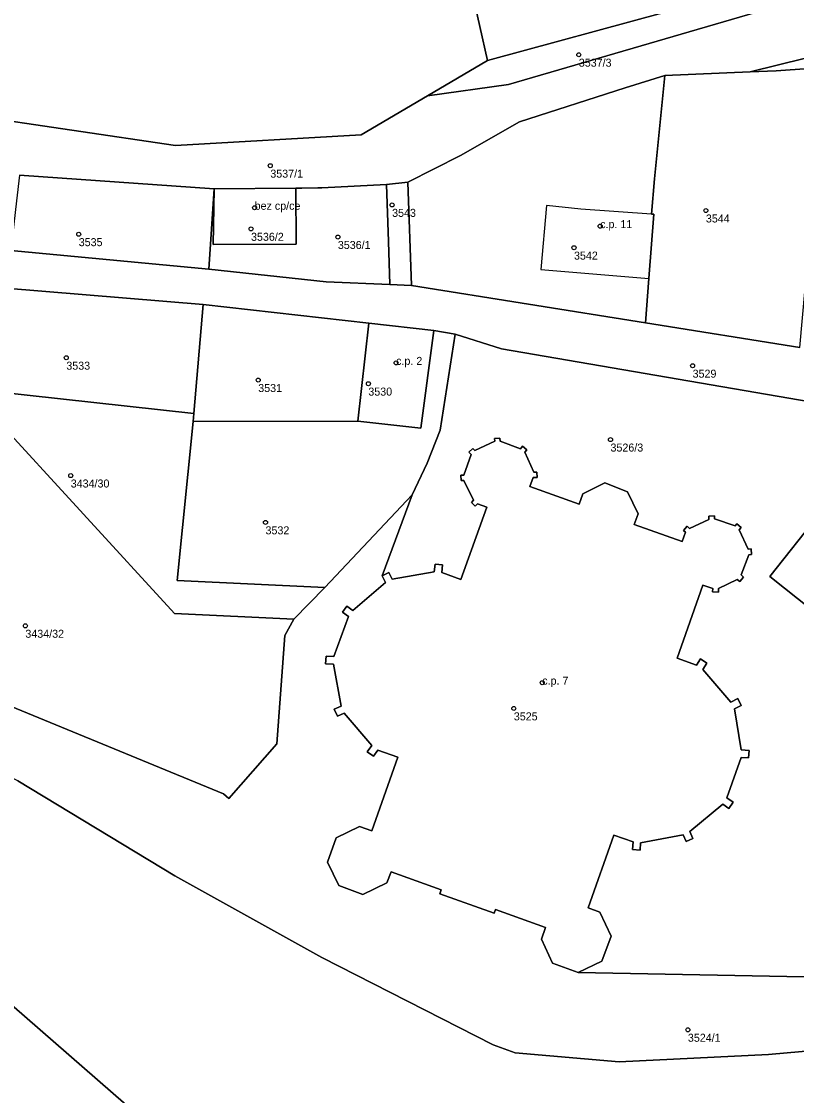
# Model space of a CAD drawing. Extents: x -878211 to -870363, y -1058464 to -1052522.
# Drawn here: x -876345.2 to -876248.4, y -1055057.5 to -1054923.3 of the extents above; entities that cross this region are included whole.
import ezdxf

# ---------------------------------------------------------------- set-up
doc = ezdxf.new("R2010")
doc.units = 0
for name, color, linetype in [('Definiční body', 7, 'Continuous'), ('Polygon budovy', 7, 'Continuous'), ('Polygon parcely', 7, 'Continuous')]:
    doc.layers.add(name, color=color, linetype=linetype)

msp = doc.modelspace()

# ---------------------------------------------------------------- linework, layer by layer
at = {"layer": 'Definiční body'}
for centre in [(-876275.58, -1054927.46994), (-876314.13, -1054941.32994), (-876316.09, -1054946.57994), (-876298.91, -1054946.22994), (-876259.7, -1054946.92994), (-876316.54, -1054949.21994), (-876272.91, -1054948.87994), (-876338.07, -1054949.88994), (-876305.69, -1054950.23994), (-876276.18, -1054951.56994), (-876339.62, -1054965.31994), (-876298.41, -1054965.95994), (-876261.36, -1054966.31994), (-876315.64, -1054968.10994), (-876301.88, -1054968.55994), (-876271.62, -1054975.54994), (-876339.07, -1054980.03994), (-876314.73, -1054985.88994), (-876344.74, -1054998.80994), (-876280.15, -1055005.90994), (-876283.7, -1055009.12994), (-876261.95, -1055049.27994)]:
    msp.add_circle(centre, 0.25, dxfattribs=at)
at = {"layer": 'Polygon budovy'}
for points in [[(-876321.14, -1054944.23), (-876321.25, -1054951.15), (-876310.9, -1054951.14), (-876310.92, -1054944.14)], [(-876280.32, -1054954.31), (-876266.83, -1054955.43), (-876266.2, -1054947.4), (-876266.5, -1054947.38), (-876275.33, -1054946.75), (-876279.63, -1054946.3)], [(-876293.7, -1054961.9), (-876301.81, -1054960.98), (-876303.2, -1054973.25), (-876295.3, -1054974.1)]]:
    msp.add_lwpolyline(points, close=True, dxfattribs=at)
for points in [[(-876274.43, -1055034.05), (-876271.2, -1055024.96), (-876268.78, -1055025.79), (-876268.87, -1055026.75), (-876267.92, -1055026.84), (-876267.86, -1055025.9), (-876262.55, -1055024.92), (-876262.17, -1055025.76), (-876261.32, -1055025.37), (-876261.69, -1055024.52), (-876257.58, -1055021.07), (-876256.82, -1055021.61), (-876256.31, -1055020.82), (-876257.09, -1055020.28), (-876255.31, -1055015.26), (-876254.38, -1055015.3), (-876254.31, -1055014.39), (-876255.27, -1055014.3), (-876256.11, -1055009.18), (-876255.27, -1055008.75), (-876255.69, -1055007.9), (-876256.57, -1055008.34), (-876260.08, -1055004.25), (-876259.58, -1055003.47), (-876260.36, -1055002.95), (-876260.88, -1055003.71), (-876263.27, -1055002.86), (-876260.09, -1054993.71), (-876258.83, -1054994.14), (-876258.86, -1054994.58), (-876258.13, -1054994.59), (-876258.12, -1054994.16), (-876255.77, -1054993.02), (-876255.44, -1054993.28), (-876254.98, -1054992.71), (-876255.3, -1054992.45), (-876254.35, -1054989.92), (-876254, -1054989.89), (-876254.04, -1054989.2), (-876254.43, -1054989.22), (-876255.55, -1054986.82), (-876255.28, -1054986.53), (-876255.84, -1054986.05), (-876256.06, -1054986.33), (-876258.61, -1054985.43), (-876258.62, -1054985.05), (-876259.32, -1054985.09), (-876259.32, -1054985.52), (-876261.73, -1054986.65), (-876262.05, -1054986.36), (-876262.5, -1054986.9), (-876262.23, -1054987.11), (-876262.67, -1054988.27), (-876268.67, -1054986.13), (-876268.18, -1054984.8), (-876269.48, -1054982.06), (-876272.32, -1054980.96), (-876275.07, -1054982.3), (-876275.55, -1054983.62), (-876281.68, -1054981.4), (-876281.27, -1054980.27), (-876280.78, -1054980.27), (-876280.84, -1054979.6), (-876281.22, -1054979.6), (-876282.32, -1054977.13), (-876282.08, -1054976.84), (-876282.62, -1054976.38), (-876282.87, -1054976.68), (-876285.4, -1054975.74), (-876285.44, -1054975.36), (-876286.11, -1054975.4), (-876286.09, -1054975.72), (-876288.56, -1054976.92), (-876288.82, -1054976.66), (-876289.32, -1054977.12), (-876289.03, -1054977.42), (-876289.94, -1054979.98), (-876290.33, -1054979.98), (-876290.29, -1054980.67), (-876289.95, -1054980.65), (-876288.73, -1054983.12), (-876289, -1054983.39), (-876288.51, -1054983.88), (-876288.24, -1054983.58), (-876287.06, -1054983.99), (-876290.32, -1054993.02), (-876292.71, -1054992.16), (-876292.6, -1054991.17), (-876293.54, -1054991.09), (-876293.64, -1054992.05), (-876298.89, -1054992.98), (-876299.31, -1054992.14), (-876300.15, -1054992.56), (-876299.72, -1054993.39), (-876303.83, -1054996.89), (-876304.57, -1054996.34), (-876305.12, -1054997.09), (-876304.36, -1054997.65), (-876306.18, -1055002.65), (-876307.15, -1055002.58), (-876307.22, -1055003.54)], [(-876307.22, -1055003.54), (-876306.24, -1055003.61), (-876305.27, -1055008.83), (-876306.15, -1055009.24), (-876305.74, -1055010.11), (-876304.89, -1055009.7), (-876301.46, -1055013.74), (-876302.01, -1055014.56), (-876301.22, -1055015.08), (-876300.69, -1055014.33), (-876298.21, -1055015.2), (-876301.45, -1055024.43), (-876302.99, -1055023.89), (-876305.92, -1055025.28), (-876306.98, -1055028.35), (-876305.58, -1055031.24), (-876302.56, -1055032.37), (-876299.57, -1055030.93), (-876299.03, -1055029.53), (-876292.76, -1055031.79), (-876292.94, -1055032.29), (-876286.14, -1055034.7), (-876285.98, -1055034.24), (-876279.73, -1055036.5), (-876280.25, -1055037.96), (-876278.88, -1055040.97), (-876275.67, -1055042.1), (-876272.69, -1055040.72), (-876271.53, -1055037.57), (-876272.96, -1055034.57), (-876274.43, -1055034.05)]]:
    msp.add_lwpolyline(points, dxfattribs=at)
at = {"layer": 'Polygon parcely'}
for points in [[(-876385.33, -1054930.06), (-876351.91, -1054934.98), (-876325.98, -1054938.79), (-876302.79, -1054937.47), (-876294.48, -1054932.58), (-876286.97, -1054928.17), (-876291.78, -1054906.9), (-876297.96, -1054890.06), (-876299.88, -1054875.09), (-876309.04, -1054869.25), (-876318.21, -1054867.84), (-876339.28, -1054874.2), (-876356, -1054887.75), (-876380.69, -1054897.58), (-876399.9, -1054901.85), (-876408.73, -1054905.38), (-876418.87, -1054910.9), (-876423.48, -1054914.13), (-876427.47, -1054915.93), (-876428.71, -1054917.43), (-876423.95, -1054924.24), (-876403.1, -1054932.35)], [(-876245.21, -1054919.74), (-876243.34, -1054905.33), (-876262.86, -1054909.66), (-876291.78, -1054906.9), (-876286.97, -1054928.17), (-876264.63, -1054922.12)], [(-876245.21, -1054919.74), (-876264.63, -1054922.12), (-876286.97, -1054928.17), (-876294.48, -1054932.58), (-876284.35, -1054931.17)], [(-876243.27, -1054928.94), (-876226.91, -1054926.9), (-876243.87, -1054927.05), (-876254.17, -1054929.61), (-876250.92, -1054929.47)], [(-876250.92, -1054929.47), (-876254.17, -1054929.61), (-876264.85, -1054930.05), (-876266.13, -1054942.96), (-876266.5, -1054947.38), (-876266.2, -1054947.4), (-876266.83, -1054955.43), (-876267.26, -1054960.95), (-876247.95, -1054964.03), (-876247.29, -1054956.62), (-876245.27, -1054933.93), (-876243.38, -1054933.76), (-876243.27, -1054928.94)], [(-876264.85, -1054930.05), (-876269.8, -1054931.6), (-876283.01, -1054935.86), (-876290.37, -1054940.07), (-876296.94, -1054943.38), (-876296.49, -1054956.28), (-876267.26, -1054960.95), (-876266.83, -1054955.43), (-876266.2, -1054947.4), (-876266.5, -1054947.38), (-876266.13, -1054942.96)], [(-876321.8, -1054954.26), (-876321.14, -1054944.23), (-876345.46, -1054942.49), (-876345.83, -1054945.71), (-876346.55, -1054951.9)], [(-876321.25, -1054951.15), (-876321.14, -1054944.23), (-876321.8, -1054954.26), (-876307.13, -1054955.82), (-876299.2, -1054956.16), (-876299.37, -1054950.78), (-876299.59, -1054943.69), (-876307.7, -1054944.11), (-876308.2, -1054944.11), (-876310.2, -1054944.13), (-876310.92, -1054944.14), (-876310.9, -1054951.14)], [(-876310.92, -1054944.14), (-876321.14, -1054944.23), (-876321.25, -1054951.15), (-876310.9, -1054951.14)], [(-876299.37, -1054950.78), (-876299.2, -1054956.16), (-876296.49, -1054956.28), (-876296.94, -1054943.38), (-876299.59, -1054943.69)], [(-876323.7, -1054972.29), (-876322.54, -1054958.67), (-876347.21, -1054956.62), (-876348.7, -1054969.52)], [(-876303.2, -1054973.25), (-876301.81, -1054960.98), (-876322.54, -1054958.67), (-876323.7, -1054972.29), (-876323.78, -1054973.29)], [(-876303.2, -1054973.25), (-876295.3, -1054974.1), (-876293.7, -1054961.9), (-876301.81, -1054960.98)], [(-876323.78, -1054973.29), (-876325.75, -1054993.15), (-876307.31, -1054994.01), (-876296.41, -1054982.45), (-876294.52, -1054978.5), (-876292.89, -1054974.37), (-876291.01, -1054962.38), (-876293.7, -1054961.9), (-876295.3, -1054974.1), (-876303.2, -1054973.25)], [(-876348.7, -1054969.52), (-876366.72, -1055000.87), (-876364.74, -1055001.39), (-876319.98, -1055019.81), (-876319.3, -1055020.38), (-876313.33, -1055013.57), (-876312.3, -1055000.03), (-876311.19, -1054997.97), (-876326.11, -1054997.28), (-876348.87, -1054972.47)], [(-876323.78, -1054973.29), (-876323.7, -1054972.29), (-876348.7, -1054969.52), (-876348.87, -1054972.47), (-876326.11, -1054997.28), (-876311.19, -1054997.97), (-876307.31, -1054994.01), (-876325.75, -1054993.15)], [(-876230.61, -1055019.14), (-876225.89, -1055023.06), (-876221.26, -1055017.49), (-876216.66, -1055021.3), (-876202.64, -1055032.79), (-876197.32, -1055029.35), (-876182.5, -1055017.11), (-876202.1, -1055003.26), (-876211.84, -1054995.38), (-876218.33, -1054990.08), (-876212.05, -1054982.01), (-876236.87, -1054973.88), (-876237.48, -1054974.65), (-876245.51, -1054984.81), (-876251.72, -1054992.65), (-876242.95, -1054999.62), (-876226.09, -1055013.5)], [(-876316.66, -1055102.83), (-876306.38, -1055081.71), (-876323.34, -1055066.32), (-876358.9, -1055035.38), (-876377.75, -1055027.25), (-876396.33, -1055052.17), (-876351.9, -1055057.99), (-876356.57, -1055092.43), (-876334.52, -1055096.3)]]:
    msp.add_lwpolyline(points, close=True, dxfattribs=at)
for points in [[(-876245.21, -1054919.74), (-876284.35, -1054931.17), (-876294.48, -1054932.58), (-876302.79, -1054937.47), (-876325.98, -1054938.79), (-876351.91, -1054934.98)], [(-876345.46, -1054942.49), (-876321.14, -1054944.23), (-876310.92, -1054944.14), (-876310.2, -1054944.13), (-876308.2, -1054944.11), (-876307.7, -1054944.11), (-876299.59, -1054943.69), (-876296.94, -1054943.38), (-876290.37, -1054940.07), (-876283.01, -1054935.86), (-876269.8, -1054931.6), (-876264.85, -1054930.05), (-876254.17, -1054929.61), (-876243.87, -1054927.05)], [(-876247.95, -1054964.03), (-876267.26, -1054960.95), (-876296.49, -1054956.28), (-876299.2, -1054956.16), (-876307.13, -1054955.82), (-876321.8, -1054954.26), (-876346.55, -1054951.9), (-876347.21, -1054956.62), (-876322.54, -1054958.67), (-876301.81, -1054960.98), (-876293.7, -1054961.9), (-876291.01, -1054962.38), (-876285.26, -1054964.19), (-876245.2, -1054971.07)], [(-876245.2, -1054971.07), (-876285.26, -1054964.19), (-876291.01, -1054962.38), (-876292.89, -1054974.37), (-876294.52, -1054978.5), (-876296.41, -1054982.45), (-876300.15, -1054992.56), (-876299.31, -1054992.14), (-876298.89, -1054992.98), (-876293.64, -1054992.05), (-876293.54, -1054991.09), (-876292.6, -1054991.17), (-876292.71, -1054992.16), (-876290.32, -1054993.02), (-876287.06, -1054983.99), (-876288.24, -1054983.58), (-876288.51, -1054983.88), (-876289, -1054983.39), (-876288.73, -1054983.12), (-876289.95, -1054980.65), (-876290.29, -1054980.67), (-876290.33, -1054979.98), (-876289.94, -1054979.98), (-876289.03, -1054977.42), (-876289.32, -1054977.12), (-876288.82, -1054976.66), (-876288.56, -1054976.92), (-876286.09, -1054975.72), (-876286.11, -1054975.4), (-876285.44, -1054975.36), (-876285.4, -1054975.74), (-876282.87, -1054976.68), (-876282.62, -1054976.38), (-876282.08, -1054976.84), (-876282.32, -1054977.13), (-876281.22, -1054979.6), (-876280.84, -1054979.6), (-876280.78, -1054980.27), (-876281.27, -1054980.27), (-876281.68, -1054981.4), (-876275.55, -1054983.62), (-876275.07, -1054982.3), (-876272.32, -1054980.96), (-876269.48, -1054982.06), (-876268.18, -1054984.8), (-876268.67, -1054986.13), (-876262.67, -1054988.27), (-876262.23, -1054987.11), (-876262.5, -1054986.9), (-876262.05, -1054986.36), (-876261.73, -1054986.65), (-876259.32, -1054985.52), (-876259.32, -1054985.09), (-876258.62, -1054985.05), (-876258.61, -1054985.43), (-876256.06, -1054986.33), (-876255.84, -1054986.05), (-876255.28, -1054986.53), (-876255.55, -1054986.82), (-876254.43, -1054989.22), (-876254.04, -1054989.2), (-876254, -1054989.89), (-876254.35, -1054989.92), (-876255.3, -1054992.45), (-876254.98, -1054992.71), (-876255.44, -1054993.28), (-876255.77, -1054993.02), (-876258.12, -1054994.16), (-876258.13, -1054994.59), (-876258.86, -1054994.58), (-876258.83, -1054994.14), (-876260.09, -1054993.71), (-876263.27, -1055002.86), (-876260.88, -1055003.71), (-876260.36, -1055002.95), (-876259.58, -1055003.47), (-876260.08, -1055004.25), (-876256.57, -1055008.34), (-876255.69, -1055007.9), (-876255.27, -1055008.75), (-876256.11, -1055009.18), (-876255.27, -1055014.3), (-876254.31, -1055014.39), (-876254.38, -1055015.3), (-876255.31, -1055015.26), (-876257.09, -1055020.28), (-876256.31, -1055020.82), (-876256.82, -1055021.61), (-876257.58, -1055021.07), (-876261.69, -1055024.52)], [(-876280.84, -1054979.6), (-876281.22, -1054979.6), (-876282.32, -1054977.13), (-876282.08, -1054976.84), (-876282.62, -1054976.38), (-876282.87, -1054976.68), (-876285.4, -1054975.74), (-876285.44, -1054975.36), (-876286.11, -1054975.4), (-876286.09, -1054975.72), (-876288.56, -1054976.92), (-876288.82, -1054976.66), (-876289.32, -1054977.12), (-876289.03, -1054977.42), (-876289.94, -1054979.98), (-876290.33, -1054979.98), (-876290.29, -1054980.67), (-876289.95, -1054980.65), (-876288.73, -1054983.12), (-876289, -1054983.39), (-876288.51, -1054983.88), (-876288.24, -1054983.58), (-876287.06, -1054983.99), (-876290.32, -1054993.02), (-876292.71, -1054992.16), (-876292.6, -1054991.17), (-876293.54, -1054991.09), (-876293.64, -1054992.05), (-876298.89, -1054992.98), (-876299.31, -1054992.14), (-876300.15, -1054992.56)], [(-876300.15, -1054992.56), (-876299.72, -1054993.39), (-876303.83, -1054996.89), (-876304.57, -1054996.34), (-876305.12, -1054997.09), (-876304.36, -1054997.65), (-876306.18, -1055002.65), (-876307.15, -1055002.58), (-876307.22, -1055003.54), (-876306.24, -1055003.61), (-876305.27, -1055008.83), (-876306.15, -1055009.24), (-876305.74, -1055010.11), (-876304.89, -1055009.7), (-876301.46, -1055013.74), (-876302.01, -1055014.56), (-876301.22, -1055015.08), (-876300.69, -1055014.33), (-876298.21, -1055015.2), (-876301.45, -1055024.43), (-876302.99, -1055023.89), (-876305.92, -1055025.28), (-876306.98, -1055028.35), (-876305.58, -1055031.24), (-876302.56, -1055032.37), (-876299.57, -1055030.93), (-876299.03, -1055029.53), (-876292.76, -1055031.79), (-876292.94, -1055032.29), (-876286.14, -1055034.7), (-876285.98, -1055034.24), (-876279.73, -1055036.5), (-876280.25, -1055037.96), (-876278.88, -1055040.97), (-876275.67, -1055042.1), (-876272.69, -1055040.72), (-876271.53, -1055037.57), (-876272.96, -1055034.57), (-876274.43, -1055034.05), (-876271.2, -1055024.96), (-876268.78, -1055025.79), (-876268.87, -1055026.75), (-876267.92, -1055026.84), (-876267.86, -1055025.9), (-876262.55, -1055024.92), (-876262.17, -1055025.76), (-876261.32, -1055025.37), (-876261.69, -1055024.52), (-876257.58, -1055021.07), (-876256.82, -1055021.61), (-876256.31, -1055020.82), (-876257.09, -1055020.28), (-876255.31, -1055015.26), (-876254.38, -1055015.3), (-876254.31, -1055014.39), (-876255.27, -1055014.3), (-876256.11, -1055009.18), (-876255.27, -1055008.75), (-876255.69, -1055007.9), (-876256.57, -1055008.34), (-876260.08, -1055004.25), (-876259.58, -1055003.47), (-876260.36, -1055002.95), (-876260.88, -1055003.71), (-876263.27, -1055002.86), (-876260.09, -1054993.71), (-876258.83, -1054994.14), (-876258.86, -1054994.58), (-876258.13, -1054994.59), (-876258.12, -1054994.16), (-876255.77, -1054993.02), (-876255.44, -1054993.28), (-876254.98, -1054992.71), (-876255.3, -1054992.45), (-876254.35, -1054989.92), (-876254, -1054989.89), (-876254.04, -1054989.2), (-876254.43, -1054989.22), (-876255.55, -1054986.82), (-876255.28, -1054986.53), (-876255.84, -1054986.05), (-876256.06, -1054986.33), (-876258.61, -1054985.43), (-876258.62, -1054985.05), (-876259.32, -1054985.09), (-876259.32, -1054985.52), (-876261.73, -1054986.65), (-876262.05, -1054986.36), (-876262.5, -1054986.9), (-876262.23, -1054987.11), (-876262.67, -1054988.27), (-876268.67, -1054986.13), (-876268.18, -1054984.8), (-876269.48, -1054982.06), (-876272.32, -1054980.96), (-876275.07, -1054982.3), (-876275.55, -1054983.62), (-876281.68, -1054981.4), (-876281.27, -1054980.27), (-876280.78, -1054980.27), (-876280.84, -1054979.6)], [(-876243.04, -1055042.76), (-876275.67, -1055042.1), (-876278.88, -1055040.97), (-876280.25, -1055037.96), (-876279.73, -1055036.5), (-876285.98, -1055034.24), (-876286.14, -1055034.7), (-876292.94, -1055032.29), (-876292.76, -1055031.79), (-876299.03, -1055029.53), (-876299.57, -1055030.93), (-876302.56, -1055032.37), (-876305.58, -1055031.24), (-876306.98, -1055028.35), (-876305.92, -1055025.28), (-876302.99, -1055023.89), (-876301.45, -1055024.43), (-876298.21, -1055015.2), (-876300.69, -1055014.33), (-876301.22, -1055015.08), (-876302.01, -1055014.56), (-876301.46, -1055013.74), (-876304.89, -1055009.7), (-876305.74, -1055010.11), (-876306.15, -1055009.24), (-876305.27, -1055008.83), (-876306.24, -1055003.61), (-876307.22, -1055003.54), (-876307.15, -1055002.58), (-876306.18, -1055002.65), (-876304.36, -1054997.65), (-876305.12, -1054997.09), (-876304.57, -1054996.34), (-876303.83, -1054996.89), (-876299.72, -1054993.39), (-876300.15, -1054992.56), (-876296.41, -1054982.45), (-876307.31, -1054994.01), (-876311.19, -1054997.97), (-876312.3, -1055000.03), (-876313.33, -1055013.57), (-876319.3, -1055020.38), (-876319.98, -1055019.81), (-876364.74, -1055001.39)], [(-876242.95, -1054999.62), (-876251.72, -1054992.65), (-876245.51, -1054984.81)], [(-876236.43, -1055051), (-876251.86, -1055052.34), (-876270.53, -1055053.27), (-876283.55, -1055052.17), (-876286.3, -1055051.17), (-876307.7, -1055040.24), (-876326.07, -1055030.03), (-876345.67, -1055018.17), (-876361.59, -1055010.4), (-876366.45, -1055010.72), (-876368.57, -1055011.46), (-876377.75, -1055027.25), (-876358.9, -1055035.38), (-876323.34, -1055066.32), (-876306.38, -1055081.71), (-876316.66, -1055102.83), (-876314.44, -1055103.64), (-876294.05, -1055111.65), (-876279.48, -1055115.89), (-876264.87, -1055113.38), (-876253.17, -1055110.11), (-876221.24, -1055096.79)], [(-876345.67, -1055018.17), (-876326.07, -1055030.03), (-876307.7, -1055040.24), (-876286.3, -1055051.17), (-876283.55, -1055052.17), (-876270.53, -1055053.27), (-876251.86, -1055052.34), (-876236.43, -1055051)], [(-876261.69, -1055024.52), (-876261.32, -1055025.37), (-876262.17, -1055025.76), (-876262.55, -1055024.92), (-876267.86, -1055025.9), (-876267.92, -1055026.84), (-876268.87, -1055026.75), (-876268.78, -1055025.79), (-876271.2, -1055024.96), (-876274.43, -1055034.05), (-876272.96, -1055034.57)], [(-876272.96, -1055034.57), (-876271.53, -1055037.57), (-876272.69, -1055040.72), (-876275.67, -1055042.1), (-876243.04, -1055042.76)]]:
    msp.add_lwpolyline(points, dxfattribs=at)

# ---------------------------------------------------------------- texts
at = {"layer": 'Definiční body'}
for s, p in [('3537/3', (-876275.58, -1054928.959)), ('3537/1', (-876314.13, -1054942.819)), ('bez cp/ce', (-876316.09, -1054946.83)), ('3543', (-876298.91, -1054947.719)), ('c.p. 11', (-876272.91, -1054949.129)), ('3544', (-876259.7, -1054948.419)), ('3535', (-876338.07, -1054951.379)), ('3536/2', (-876316.54, -1054950.709)), ('3536/1', (-876305.69, -1054951.729)), ('3542', (-876276.18, -1054953.059)), ('c.p. 2', (-876298.41, -1054966.21)), ('3533', (-876339.62, -1054966.809)), ('3529', (-876261.36, -1054967.809)), ('3531', (-876315.64, -1054969.599)), ('3530', (-876301.88, -1054970.049)), ('3526/3', (-876271.62, -1054977.039)), ('3434/30', (-876339.07, -1054981.529)), ('3532', (-876314.73, -1054987.379)), ('3434/32', (-876344.74, -1055000.299)), ('c.p. 7', (-876280.15, -1055006.159)), ('3525', (-876283.7, -1055010.619)), ('3524/1', (-876261.95, -1055050.769))]:
    msp.add_text(s, height=0.999996, dxfattribs=at).set_placement(p)

doc.saveas('drawing.dxf')
